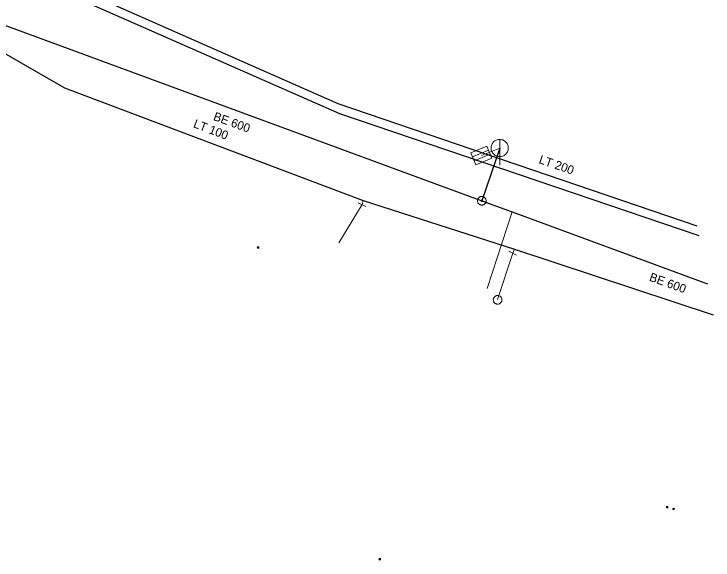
# Model space of a CAD drawing. Extents: x -783064 to -782702, y -1007904 to -1007145.
# Drawn here: x -782859.9 to -782778.9, y -1007278.7 to -1007215.4 of the extents above; entities that cross this region are included whole.
import ezdxf

# ---------------------------------------------------------------- set-up
doc = ezdxf.new("R2010")
doc.units = 0
doc.header["$LTSCALE"] = 0.4
doc.header["$PDMODE"] = 32
doc.header["$PDSIZE"] = 0.2
for name, color, linetype, lineweight in [('1', 7, 'Continuous', 13), ('11', 7, 'Continuous', 13), ('13', 7, 'Continuous', 13), ('14', 7, 'Continuous', 13), ('17', 7, 'Continuous', 25), ('22', 7, 'Continuous', 13), ('23', 7, 'Continuous', 13), ('31', 7, 'Continuous', 13), ('34', 7, 'Continuous', 13)]:
    doc.layers.add(name, color=color, linetype=linetype, lineweight=lineweight)

msp = doc.modelspace()

# ---------------------------------------------------------------- linework, layer by layer
at = {"layer": '1'}
for p in [(-782831.626, -1007242.467), (-782784.23, -1007272.579), (-782783.48, -1007272.78), (-782817.52, -1007278.599)]:
    msp.add_point(p, dxfattribs=at)
at = {"layer": '11'}
for p, q in [((-782805.755, -1007231.803), (-782803.629, -1007230.931)), ((-782805.086, -1007247.208), (-782802.202, -1007238.338))]:
    msp.add_line(p, q, dxfattribs=at)
at = {"layer": '13'}
for p, q in [((-782819.58, -1007237.498), (-782822.268, -1007241.919)), ((-782802.116, -1007243.126), (-782803.88, -1007248.501))]:
    msp.add_line(p, q, dxfattribs=at)
at = {"layer": '14', "lineweight": 25}
for p in [(-782861.079, -1007216.63), (-782803.629, -1007230.931)]:
    msp.add_line(p, (-782805.701, -1007237.048), dxfattribs=at)
at = {"layer": '14'}
for p, q in [((-782819.462, -1007237.013), (-782819.58, -1007237.498)), ((-782801.929, -1007242.663), (-782802.116, -1007243.126))]:
    msp.add_line(p, q, dxfattribs=at)
at = {"layer": '14', "lineweight": 25}
msp.add_lwpolyline([(-782805.701, -1007237.048), (-782802.202, -1007238.338), (-782779.546, -1007246.691)], dxfattribs=at)
at = {"layer": '17'}
for points in [[(-782780.739, -1007239.982), (-782822.337, -1007225.824), (-782856.072, -1007210.901), (-782877.582, -1007199.233), (-782894.804, -1007187.137)], [(-782894.804, -1007187.137), (-782878.263, -1007200.064), (-782855.822, -1007212.077), (-782822.195, -1007226.94), (-782780.544, -1007241.082)], [(-782865.675, -1007217.253), (-782854.039, -1007223.95), (-782819.462, -1007237.013), (-782801.929, -1007242.663), (-782778.91, -1007250.271)]]:
    msp.add_lwpolyline(points, dxfattribs=at)
at = {"layer": '22'}
for p, q in [((-782803.629, -1007232.931), (-782803.628, -1007229.931)), ((-782806.787, -1007231.949), (-782804.937, -1007231.19)), ((-782806.597, -1007232.411), (-782804.747, -1007231.652))]:
    msp.add_line(p, q, dxfattribs=at)
for points in [[(-782802.629, -1007230.931), (-782802.634, -1007230.822), (-782802.652, -1007230.714), (-782802.682, -1007230.608), (-782802.722, -1007230.507), (-782802.774, -1007230.41), (-782802.836, -1007230.32), (-782802.908, -1007230.237), (-782802.988, -1007230.163), (-782803.076, -1007230.097), (-782803.17, -1007230.042), (-782803.27, -1007229.997), (-782803.375, -1007229.964), (-782803.482, -1007229.942), (-782803.591, -1007229.932), (-782803.701, -1007229.934), (-782803.809, -1007229.948), (-782803.916, -1007229.973), (-782804.019, -1007230.01), (-782804.117, -1007230.059), (-782804.209, -1007230.117), (-782804.295, -1007230.186), (-782804.372, -1007230.263), (-782804.441, -1007230.349), (-782804.5, -1007230.441), (-782804.548, -1007230.539), (-782804.585, -1007230.642), (-782804.611, -1007230.749), (-782804.625, -1007230.857), (-782804.628, -1007230.967), (-782804.618, -1007231.076), (-782804.597, -1007231.183), (-782804.563, -1007231.287), (-782804.519, -1007231.387), (-782804.464, -1007231.482), (-782804.398, -1007231.57), (-782804.324, -1007231.65), (-782804.241, -1007231.722), (-782804.151, -1007231.784), (-782804.055, -1007231.836), (-782803.953, -1007231.877), (-782803.848, -1007231.907), (-782803.74, -1007231.925), (-782803.63, -1007231.931), (-782803.521, -1007231.925), (-782803.413, -1007231.907), (-782803.308, -1007231.878), (-782803.206, -1007231.837), (-782803.109, -1007231.785), (-782803.019, -1007231.723), (-782802.936, -1007231.652), (-782802.861, -1007231.572), (-782802.796, -1007231.484), (-782802.74, -1007231.39), (-782802.696, -1007231.29), (-782802.662, -1007231.186), (-782802.64, -1007231.078), (-782802.63, -1007230.969)], [(-782806.977, -1007231.486), (-782805.127, -1007230.727), (-782804.557, -1007232.115), (-782806.408, -1007232.874)]]:
    msp.add_lwpolyline(points, close=True, dxfattribs=at)
at = {"layer": '23'}
for points in [[(-782803.673, -1007248.07), (-782803.723, -1007248.052), (-782803.774, -1007248.039), (-782803.825, -1007248.033), (-782803.878, -1007248.031), (-782803.93, -1007248.035), (-782803.982, -1007248.045), (-782804.032, -1007248.059), (-782804.08, -1007248.079), (-782804.126, -1007248.103), (-782804.169, -1007248.133), (-782804.21, -1007248.166), (-782804.247, -1007248.205), (-782804.278, -1007248.245), (-782804.305, -1007248.289), (-782804.329, -1007248.336), (-782804.346, -1007248.387), (-782804.359, -1007248.436), (-782804.366, -1007248.49), (-782804.368, -1007248.54), (-782804.365, -1007248.593), (-782804.354, -1007248.645), (-782804.34, -1007248.695), (-782804.32, -1007248.744), (-782804.296, -1007248.791), (-782804.266, -1007248.833), (-782804.232, -1007248.873), (-782804.195, -1007248.909), (-782804.153, -1007248.941), (-782804.108, -1007248.968), (-782804.062, -1007248.992), (-782804.013, -1007249.01), (-782803.962, -1007249.022), (-782803.909, -1007249.029), (-782803.858, -1007249.031), (-782803.806, -1007249.026), (-782803.754, -1007249.017), (-782803.704, -1007249.003), (-782803.655, -1007248.983), (-782803.609, -1007248.958)], [(-782804.366, -1007248.49), (-782804.368, -1007248.54), (-782804.365, -1007248.593), (-782804.354, -1007248.645), (-782804.34, -1007248.695), (-782804.32, -1007248.744), (-782804.296, -1007248.791), (-782804.266, -1007248.833), (-782804.232, -1007248.873), (-782804.195, -1007248.909), (-782804.153, -1007248.941), (-782804.108, -1007248.968), (-782804.062, -1007248.992), (-782804.013, -1007249.01), (-782803.962, -1007249.022), (-782803.909, -1007249.029), (-782803.858, -1007249.031), (-782803.806, -1007249.026), (-782803.754, -1007249.017), (-782803.704, -1007249.003), (-782803.655, -1007248.983), (-782803.609, -1007248.958), (-782803.566, -1007248.93), (-782803.526, -1007248.895), (-782803.489, -1007248.859), (-782803.458, -1007248.816), (-782803.431, -1007248.772), (-782803.407, -1007248.725), (-782803.39, -1007248.676), (-782803.377, -1007248.625), (-782803.37, -1007248.573), (-782803.369, -1007248.521), (-782803.372, -1007248.468), (-782803.381, -1007248.417), (-782803.397, -1007248.367), (-782803.415, -1007248.318), (-782803.44, -1007248.273), (-782803.47, -1007248.228), (-782803.504, -1007248.188), (-782803.541, -1007248.152)], [(-782803.609, -1007248.958), (-782803.566, -1007248.93), (-782803.526, -1007248.895), (-782803.489, -1007248.859), (-782803.458, -1007248.816), (-782803.431, -1007248.772), (-782803.407, -1007248.725), (-782803.39, -1007248.676), (-782803.377, -1007248.625), (-782803.37, -1007248.573), (-782803.369, -1007248.521), (-782803.372, -1007248.468), (-782803.381, -1007248.417), (-782803.397, -1007248.367), (-782803.415, -1007248.318), (-782803.44, -1007248.273), (-782803.47, -1007248.228), (-782803.504, -1007248.188), (-782803.541, -1007248.152), (-782803.583, -1007248.121), (-782803.627, -1007248.093), (-782803.673, -1007248.07), (-782803.723, -1007248.052), (-782803.774, -1007248.039), (-782803.825, -1007248.033), (-782803.878, -1007248.031), (-782803.93, -1007248.035), (-782803.982, -1007248.045), (-782804.032, -1007248.059), (-782804.08, -1007248.079), (-782804.126, -1007248.103), (-782804.169, -1007248.133), (-782804.21, -1007248.166), (-782804.247, -1007248.205), (-782804.278, -1007248.245), (-782804.305, -1007248.289), (-782804.329, -1007248.336), (-782804.346, -1007248.387), (-782804.359, -1007248.436), (-782804.366, -1007248.49)], [(-782803.541, -1007248.152), (-782803.583, -1007248.121), (-782803.627, -1007248.093), (-782803.673, -1007248.07)]]:
    msp.add_lwpolyline(points, dxfattribs=at)
at = {"layer": '31'}
for points in [[(-782805.231, -1007237.22), (-782805.216, -1007237.171), (-782805.206, -1007237.119), (-782805.202, -1007237.067), (-782805.201, -1007237.015), (-782805.208, -1007236.963), (-782805.22, -1007236.911), (-782805.237, -1007236.862), (-782805.259, -1007236.815), (-782805.285, -1007236.77), (-782805.316, -1007236.728), (-782805.352, -1007236.689), (-782805.392, -1007236.655), (-782805.434, -1007236.625), (-782805.48, -1007236.599), (-782805.528, -1007236.578), (-782805.577, -1007236.563), (-782805.629, -1007236.553), (-782805.682, -1007236.548), (-782805.733, -1007236.548), (-782805.785, -1007236.555), (-782805.837, -1007236.567), (-782805.886, -1007236.584), (-782805.934, -1007236.605), (-782805.979, -1007236.632), (-782806.02, -1007236.663), (-782806.059, -1007236.699), (-782806.094, -1007236.738), (-782806.123, -1007236.781), (-782806.149, -1007236.827), (-782806.17, -1007236.875), (-782806.185, -1007236.924), (-782806.195, -1007236.976), (-782806.201, -1007237.028), (-782806.2, -1007237.08), (-782806.193, -1007237.132), (-782806.182, -1007237.183), (-782806.165, -1007237.233), (-782806.144, -1007237.281), (-782806.116, -1007237.326), (-782806.085, -1007237.367), (-782806.049, -1007237.406), (-782806.011, -1007237.44), (-782805.967, -1007237.47), (-782805.921, -1007237.496), (-782805.873, -1007237.517), (-782805.824, -1007237.532), (-782805.772, -1007237.542), (-782805.721, -1007237.547), (-782805.668, -1007237.547), (-782805.616, -1007237.54), (-782805.565, -1007237.529), (-782805.516, -1007237.512), (-782805.468, -1007237.49), (-782805.423, -1007237.463), (-782805.381, -1007237.432), (-782805.342, -1007237.396), (-782805.308, -1007237.357), (-782805.278, -1007237.314), (-782805.252, -1007237.268)], [(-782805.624, -1007237.076), (-782805.62, -1007237.067), (-782805.62, -1007237.059), (-782805.619, -1007237.051), (-782805.619, -1007237.042), (-782805.62, -1007237.034), (-782805.622, -1007237.025), (-782805.624, -1007237.017), (-782805.628, -1007237.009), (-782805.633, -1007237.002), (-782805.637, -1007236.995), (-782805.644, -1007236.989), (-782805.65, -1007236.983), (-782805.657, -1007236.978), (-782805.664, -1007236.974), (-782805.672, -1007236.971), (-782805.681, -1007236.967), (-782805.689, -1007236.967), (-782805.697, -1007236.966), (-782805.706, -1007236.966), (-782805.714, -1007236.967), (-782805.723, -1007236.969), (-782805.731, -1007236.971), (-782805.739, -1007236.975), (-782805.747, -1007236.979), (-782805.753, -1007236.984), (-782805.759, -1007236.991), (-782805.765, -1007236.997), (-782805.77, -1007237.004), (-782805.774, -1007237.011), (-782805.777, -1007237.019), (-782805.781, -1007237.028), (-782805.781, -1007237.036), (-782805.782, -1007237.044), (-782805.782, -1007237.053), (-782805.781, -1007237.061), (-782805.78, -1007237.069), (-782805.777, -1007237.078), (-782805.773, -1007237.086), (-782805.769, -1007237.094), (-782805.764, -1007237.1), (-782805.757, -1007237.106), (-782805.751, -1007237.112), (-782805.744, -1007237.117), (-782805.737, -1007237.121), (-782805.729, -1007237.124), (-782805.72, -1007237.128), (-782805.712, -1007237.128), (-782805.704, -1007237.129), (-782805.695, -1007237.129), (-782805.687, -1007237.128), (-782805.679, -1007237.127), (-782805.67, -1007237.124), (-782805.662, -1007237.12), (-782805.655, -1007237.115), (-782805.648, -1007237.111), (-782805.642, -1007237.104), (-782805.636, -1007237.098), (-782805.631, -1007237.091), (-782805.627, -1007237.084)]]:
    msp.add_lwpolyline(points, close=True, dxfattribs=at)
at = {"layer": '34'}
for p, q in [((-782820.024, -1007237.269), (-782819.135, -1007237.727)), ((-782802.56, -1007242.897), (-782801.671, -1007243.355))]:
    msp.add_line(p, q, dxfattribs=at)

# ---------------------------------------------------------------- texts
at = {"layer": '1'}
for s, rotation, p in [('BE 600', 340, (-782836.891, -1007227.663)), ('LT 100', 339, (-782839.209, -1007228.499)), ('LT 200', 341, (-782799.168, -1007232.668)), ('BE 600', 340, (-782786.376, -1007246.288))]:
    msp.add_text(s, height=1, rotation=rotation, dxfattribs=at).set_placement(p)

doc.saveas('drawing.dxf')
